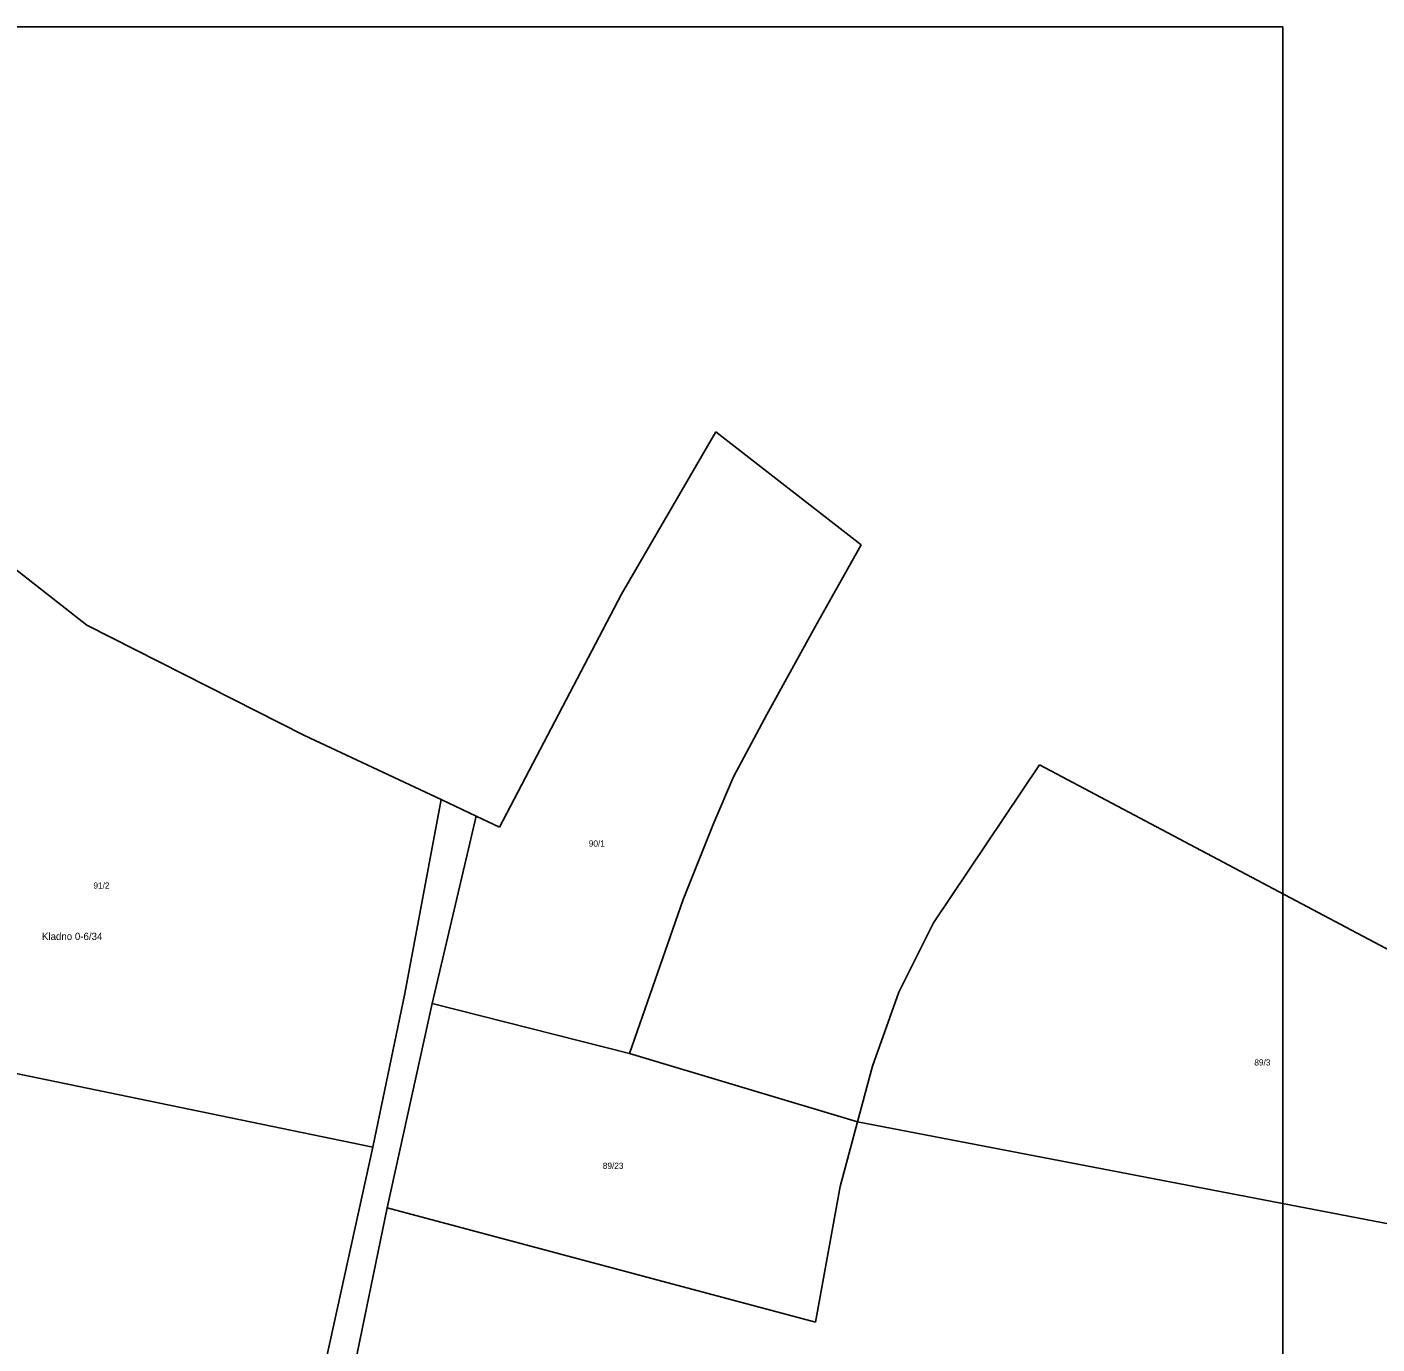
# Model space of a CAD drawing. Extents: x -752500 to -750336, y -1035826 to -1033500.
# Drawn here: x -751596.3 to -751224, y -1033863.2 to -1033500 of the extents above; entities that cross this region are included whole.
import ezdxf

# ---------------------------------------------------------------- set-up
doc = ezdxf.new("R2010")
doc.units = 0
for name, color, linetype in [('Hranice kat_území', 7, 'Continuous'), ('Hranice parcel', 7, 'Continuous'), ('ML1000', 7, 'Continuous'), ('Parcelní čísla', 7, 'Continuous')]:
    doc.layers.add(name, color=color, linetype=linetype)

msp = doc.modelspace()

# ---------------------------------------------------------------- linework, layer by layer
at = {"layer": 'Hranice kat_území'}
for p, q in [((-751432.36, -1033656.36), (-751406.36, -1033611.68)), ((-751366.27, -1033642.79), (-751406.36, -1033611.68)), ((-751366.27, -1033642.79), (-751378.36, -1033664.44)), ((-751600.62, -1033648.57), (-751579.75, -1033664.94)), ((-751465.94, -1033720.63), (-751432.36, -1033656.36)), ((-751378.36, -1033664.44), (-751392.26, -1033689.59)), ((-751519.79, -1033695.33), (-751579.75, -1033664.94)), ((-751392.26, -1033689.59), (-751401.45, -1033706.8)), ((-751482.05, -1033713.06), (-751519.79, -1033695.33)), ((-751317.11, -1033703.46), (-751346.3, -1033747.02)), ((-751317.11, -1033703.46), (-751214.33, -1033757.93)), ((-751401.45, -1033706.8), (-751406.85, -1033719.41)), ((-751472.45, -1033717.57), (-751482.05, -1033713.06)), ((-751465.94, -1033720.63), (-751472.45, -1033717.57)), ((-751406.85, -1033719.41), (-751415.3, -1033740.6)), ((-751415.3, -1033740.6), (-751430.13, -1033783.1)), ((-751346.3, -1033747.02), (-751355.9, -1033766.12)), ((-751355.9, -1033766.12), (-751363.15, -1033786.6)), ((-751430.13, -1033783.1), (-751367.27, -1033801.87)), ((-751363.15, -1033786.6), (-751367.27, -1033801.87))]:
    msp.add_line(p, q, dxfattribs=at)
at = {"layer": 'Hranice parcel'}
for p, q in [((-751492.13, -1033766.53), (-751482.05, -1033713.06)), ((-751484.53, -1033769.24), (-751472.45, -1033717.57)), ((-751500.87, -1033808.86), (-751492.13, -1033766.53)), ((-751496.99, -1033825.66), (-751484.53, -1033769.24)), ((-751484.53, -1033769.24), (-751430.13, -1033783.1)), ((-751674.33, -1033773.12), (-751500.87, -1033808.86)), ((-751367.27, -1033801.87), (-751372.02, -1033819.73)), ((-751149.74, -1033843.74), (-751367.27, -1033801.87)), ((-751500.87, -1033808.86), (-751532.72, -1033953.48)), ((-751372.02, -1033819.73), (-751378.86, -1033857.15)), ((-751496.99, -1033825.66), (-751532.03, -1033996.81)), ((-751378.86, -1033857.15), (-751496.99, -1033825.66))]:
    msp.add_line(p, q, dxfattribs=at)
at = {"layer": 'ML1000'}
for points in [[(-752500, -1033500), (-751875, -1033500), (-751250, -1033500)], [(-751250, -1035000), (-751250, -1034500), (-751250, -1034000), (-751250, -1033500)]]:
    msp.add_lwpolyline(points, dxfattribs=at)

# ---------------------------------------------------------------- texts
msp.add_text('Kladno 0-6/34', height=2, dxfattribs=at).set_placement((-751592.14, -1033751.76))
at = {"layer": 'Parcelní čísla'}
for s, p in [('90/1', (-751441.36, -1033726.01)), ('91/2', (-751577.95, -1033737.6)), ('89/3', (-751257.84, -1033786.36)), ('89/23', (-751437.49, -1033814.87))]:
    msp.add_text(s, height=1.7, dxfattribs=at).set_placement(p)

doc.saveas('drawing.dxf')
